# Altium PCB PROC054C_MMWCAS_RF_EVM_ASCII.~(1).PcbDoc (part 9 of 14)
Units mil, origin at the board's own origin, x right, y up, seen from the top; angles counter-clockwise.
Board outline 6299.21 x 5370.07 mil, 8 copper layers (L1 TOP, L2 GND, L3 SIGNAL 1, L4 GND, L5 SIGNAL 2, L6 SIGNAL 3, L7 GND, L8 BOTTOM), stack 53.5 mil thick; 775 components, 552 nets, 2648 pads, 7845 vias.
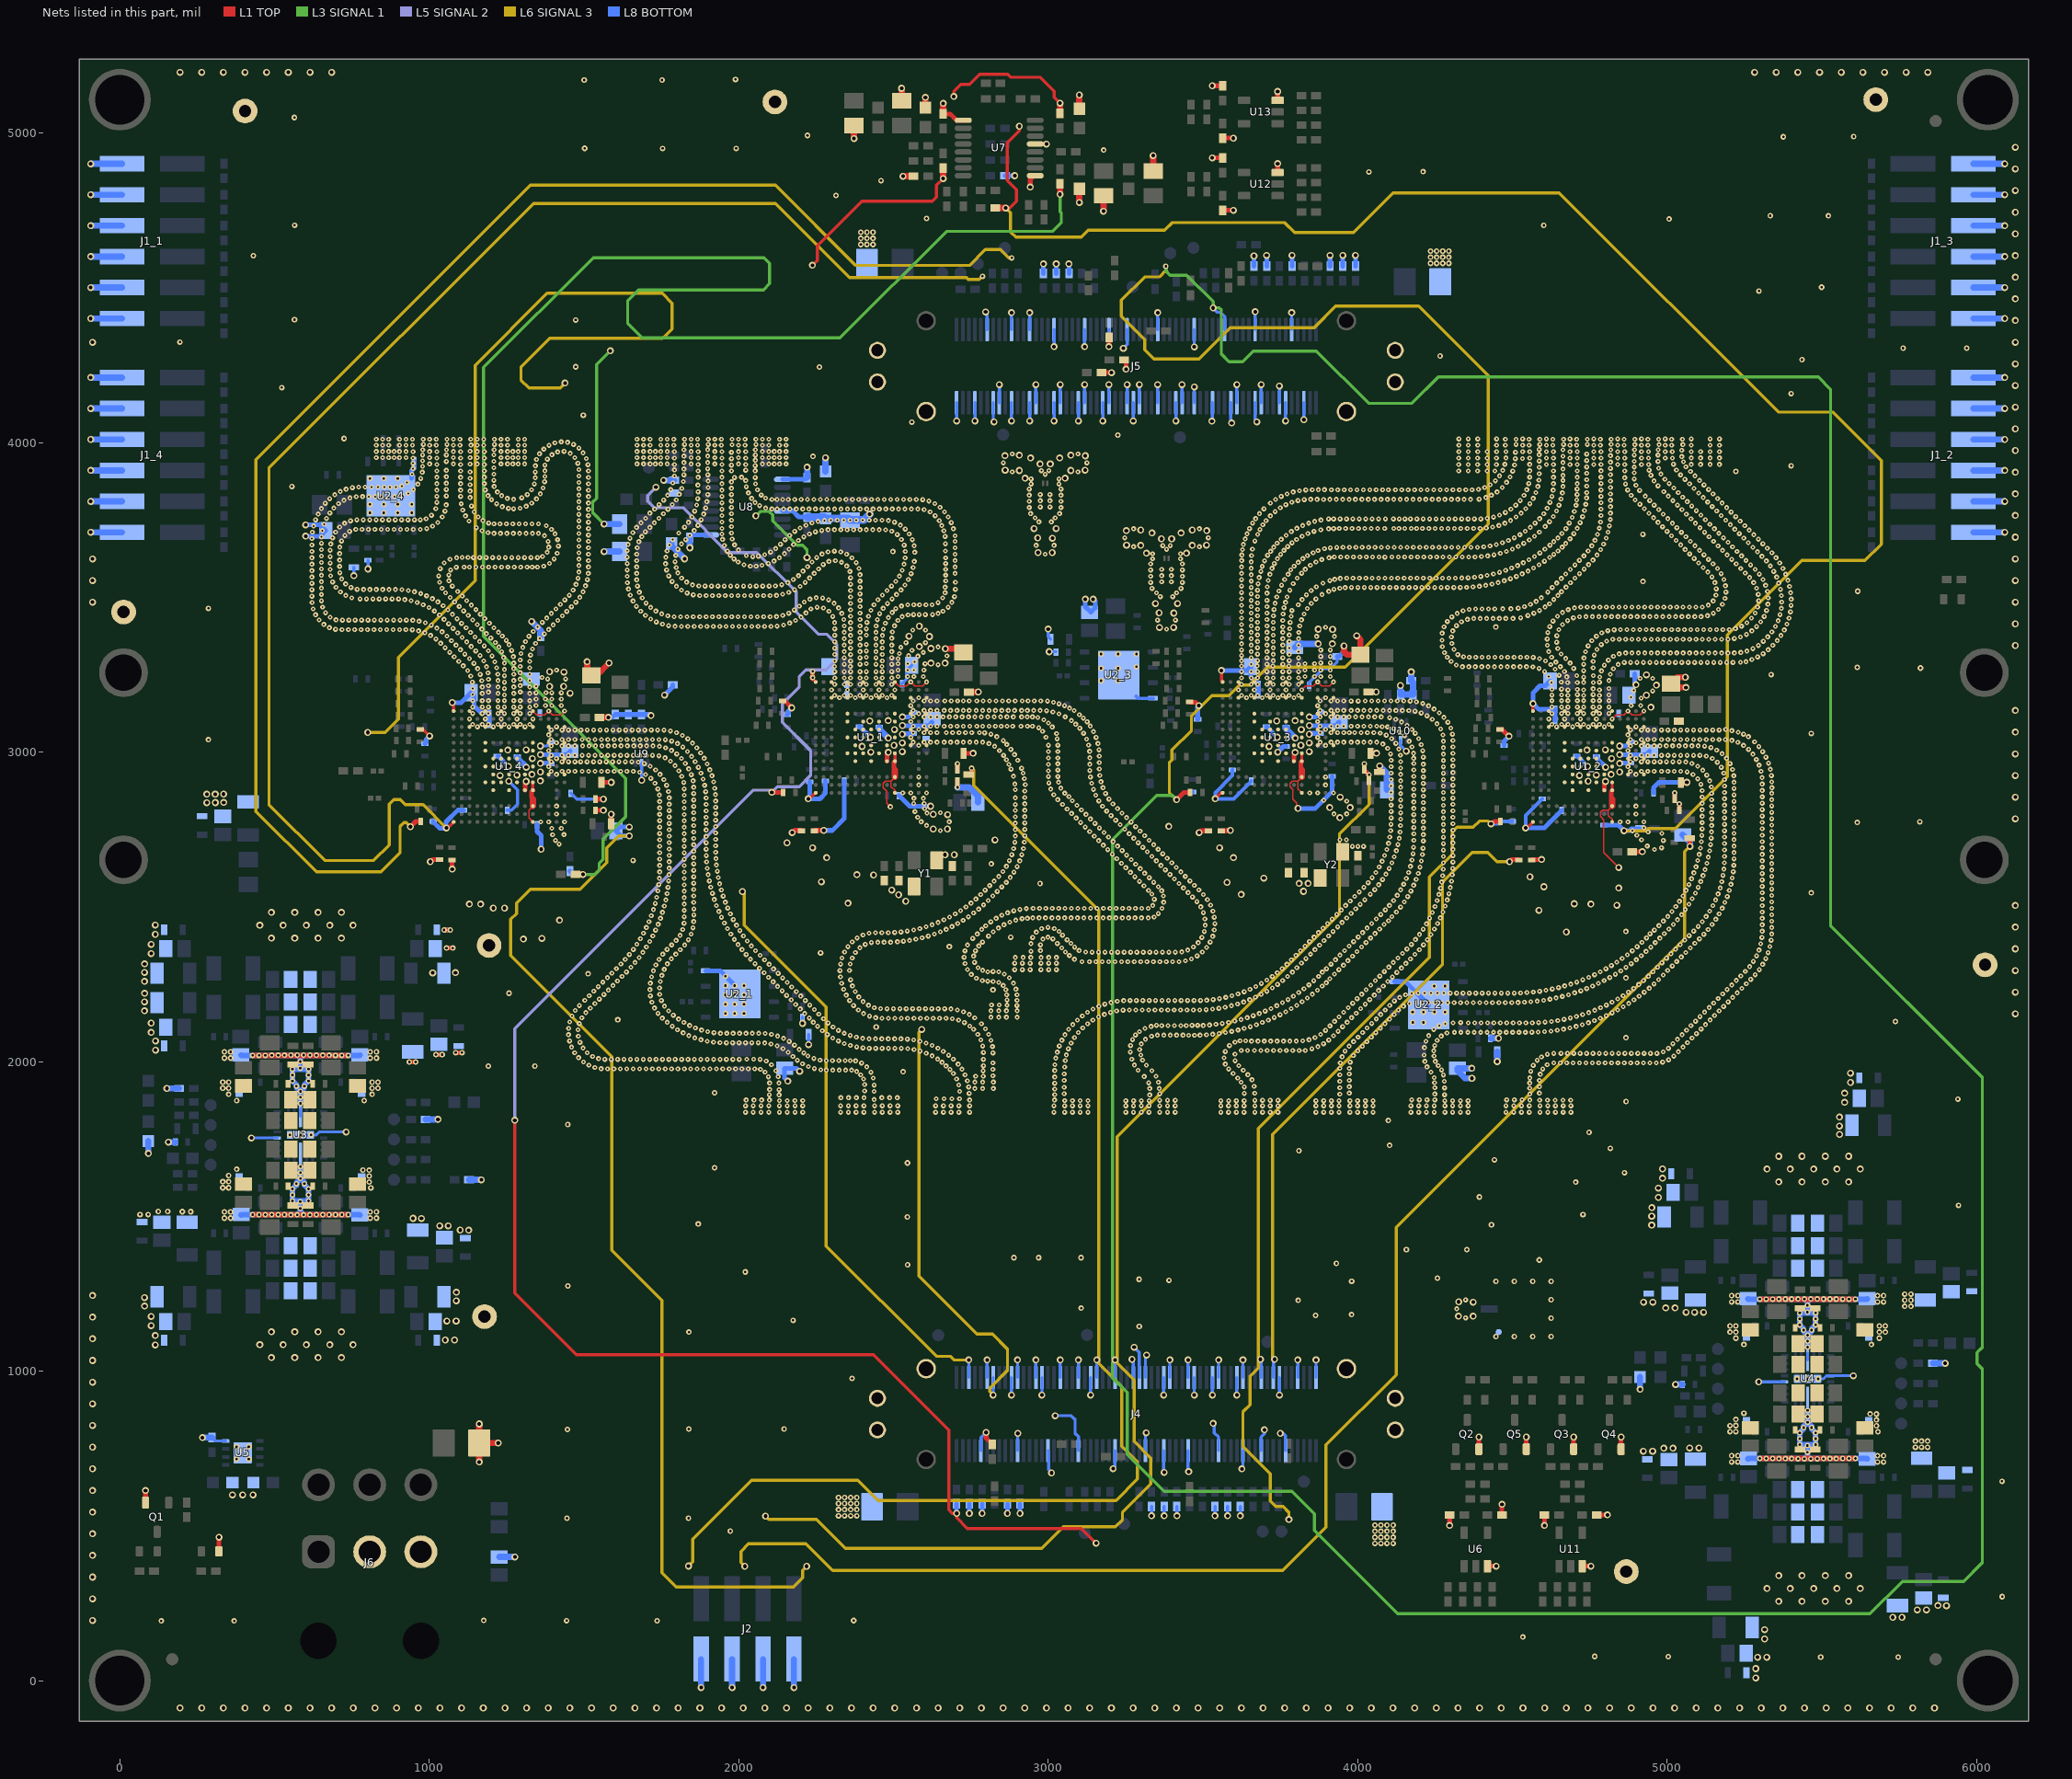
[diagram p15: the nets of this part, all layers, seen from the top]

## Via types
v1: diameter 13.77/15.74 (per signal layer), hole 5.9, L1 TOP to L2 GND, tented both sides, 5522 vias
v2: diameter 22.4, hole 12.2, L1 TOP to L8 BOTTOM, tented both sides, 1522 vias
v3: diameter 18, hole 8, L1 TOP to L8 BOTTOM, tented both sides, 727 vias
v4: diameter 18, hole 7.87, L1 TOP to L8 BOTTOM, tented top, 50 vias
v5: diameter 24, hole 12, L1 TOP to L8 BOTTOM, tented both sides, 13 vias
v6: diameter 19.68, hole 7.87, L1 TOP to L8 BOTTOM, tented top, 10 vias
v7: diameter 13.77/15.74 (per signal layer), hole 5.9, L1 TOP to L2 GND, tented top, 1 vias

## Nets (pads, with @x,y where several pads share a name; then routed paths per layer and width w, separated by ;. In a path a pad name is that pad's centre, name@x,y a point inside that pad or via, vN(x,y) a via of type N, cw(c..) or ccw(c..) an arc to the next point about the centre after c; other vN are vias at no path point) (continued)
GND: (continued)
  other v1: 4302.03,3293.21 4761.3,3293.07 2361.36,3294.31 4607.12,3294.44 1176.12,3294.76 2310.19,3294.52 2463.73,3294.69 3625,3295 3727.55,3295.32 3778.73,3295.48 3676.36,3295.67 4810.13,3296.99 1293.92,3297.69 5273.94,3299.28 1129.92,3301.76 2514.91,3302.12 4588,3302.28 4672.25,3302.38 2340.87,3304.39 2392.04,3304.39 2443.23,3304.39 2494.41,3304.39 3655.87,3304.39 3707.04,3304.39 3758.23,3304.39 3809.41,3304.39 4731.5,3304.16 1240.19,3305.75 2412.55,3306.28 4360.98,3306.4 4381.65,3306.4 4402.32,3306.4 4422.99,3306.4 4443.66,3306.4 4464.33,3306.4 4485,3306.4 4505.67,3306.4 4526.34,3306.4 4547.01,3306.4 4567.67,3306.06 4627.18,3306.36 4289.5,3306.5 5292.9,3307.5 1080.42,3307.88 1271.44,3308.32 4342,3308 3881.09,3308.94 3911.77,3308.94 1202.52,3310.38 2579.46,3310.11 4826.52,3309.57 2549.28,3311.33 2672.88,3311 1164.35,3311.76 3625,3312 4764.92,3313.42 1326.93,3313.59 2310.19,3315.19 2361.36,3314.98 2463.73,3315.36 4323.73,3314.9 1115.3,3316.38 3676.36,3316.34 3727.55,3315.99 3778.73,3316.15 4657.68,3317.04 1296.54,3318.19 4845.59,3317.55 5310.67,3318.07 2519.3,3318.51 4866.07,3320.39 4886.74,3320.4 4907.41,3320.4 4928.08,3320.4 4948.75,3320.4 4969.42,3320.4 4990.09,3320.4 5010.76,3320.4 5031.43,3320.4 5052.1,3320.4 5072.77,3320.4 5093.44,3320.4 5114.11,3320.4 5134.78,3320.4 5155.45,3320.4 5176.12,3320.4 5196.79,3320.4 5217.46,3320.4 2596.3,3322.1 4280.75,3321.51 5238.08,3321.78 1065.8,3322.5 1233.97,3323.98 4736.21,3324.29 2340.87,3325.06 2392.04,3325.06 2443.23,3325.06 2494.41,3325.06 3655.87,3325.06 3707.04,3325.06 3758.23,3325.06 3809.41,3325.06 4617.8,3324.78 5258.24,3326.37 1150.09,3326.71 2412.55,3326.95 1191.01,3327.55 1266.15,3328.31 2559.91,3329.05 3625.19,3329.64 3881.09,3329.61 3911.77,3329.61 1100.69,3330.99 5326.95,3330.81 4311.43,3331.51 4773.84,3332.07 1333.33,3333.24 5277.42,3334.05 4646.86,3334.65 2310.19,3335.86 2361.36,3335.65 2463.94,3336.02 1051.18,3337.12 3676.36,3337.01 3727.55,3336.66 3778.73,3336.82 1302.22,3338.06 2523.91,3338.46 1225.21,3339.7 2644,3339.89 1135.47,3341.33 4273.84,3340.99 1177.23,3342.95 4744.67,3343.14 4613.08,3344.9 5295.17,3344.65 5341.75,3345.24 1086.07,3345.61 2340.87,3345.73 2392.04,3345.73 2443.23,3345.73 2494.41,3345.73 3655.87,3345.73 3707.04,3345.73 3758.23,3345.73 3809.41,3345.73 1257.52,3347.09 2412.55,3347.62 4787.42,3347.65 3625.19,3350.31 1343.4,3351.29 4304.52,3350.99 1036.57,3351.73 2540.8,3353.49 1213.52,3353.77 2603.43,3353.58 4643.23,3355 1120.85,3355.95 2361.36,3356.32 2463.73,3356.03 1310.81,3356.86 2310.19,3356.53 3727.55,3357.33 3778.73,3357.49 1162.61,3357.57 3676.36,3357.68 5311.03,3357.9 4804.88,3358.72 1071.45,3360.23 4756.59,3360.03 5355.82,3360.38 1249,3361 4272.55,3361.62 4824.81,3364.21 1021.15,3365.5 4845.47,3364.72 4866.14,3364.72 4886.81,3364.72 4907.48,3364.72 4928.15,3364.72 4948.82,3364.72 4969.49,3364.72 4990.16,3364.72 5010.83,3364.72 5031.5,3364.72 5052.17,3364.72 5072.84,3364.72 5093.51,3364.72 5114.18,3364.72 5134.85,3364.72 5155.52,3364.72 5176.19,3364.72 5196.86,3364.75 2340.87,3366.4 2392.04,3366.4 2443.23,3366.4 3655.87,3366.4 3707.04,3366.4 3758.23,3366.4 3809.41,3366.4 4612.55,3365.57 1356.76,3367.07 5217.43,3366.81 1198.9,3368.39 2494.41,3367.88 1106.24,3370.56 3625.19,3370.98 1147.99,3372.19 4303.23,3371.62 5237.41,3372.09 5325.61,3372.56 1322.13,3374.16 3867.54,3374 3925.32,3374 4771.56,3374.29 1056.84,3374.84 1236,3375 4643.91,3375.66 1003.94,3376.95 2310.19,3377.29 2361.36,3377.02 2464.04,3376.7 5368.24,3376.9 2412.55,3377.64 3676.36,3378.35 3727.55,3378 3778.77,3378.16 5256.32,3380.44 1371.38,3381.69 1184.29,3383 4273.49,3384.45 1091.62,3385.18 4789.11,3385.21 985.27,3385.81 4614.64,3386.13 1133.38,3386.8 1223.45,3387.22 2340.87,3387.07 2392.04,3387.07 2443.23,3387.07 3655.87,3387.07 3707.04,3387.07 3758.23,3387.07 3809.92,3387.06 2496.7,3388.42 5338.86,3388.43 1041.41,3388.6 1335.89,3389.58 965.52,3391.92 3625.19,3391.65 4307.31,3391.88 4808.52,3392.32 5273.68,3391.67 2562.57,3394.44 2603.42,3394.43 945.1,3395.14 4650.08,3395.38 4828.97,3395.31 4849.64,3395.4 4870.31,3395.4 4890.98,3395.4 4911.65,3395.4 4932.32,3395.4 4952.99,3395.4 4973.66,3395.4 4994.33,3395.4 5015,3395.4 5035.67,3395.4 5056.34,3395.4 5077.01,3395.4 5097.68,3395.4 5118.35,3395.4 5139.02,3395.4 5159.69,3395.4 5180.36,3395.4 5378.83,3394.65 717.74,3395.66 738.41,3395.66 759.08,3395.66 779.75,3395.66 800.42,3395.66 821.09,3395.66 841.76,3395.66 862.43,3395.66 883.1,3395.66 903.77,3395.66 924.44,3395.66 1385.99,3396.3 5201.03,3395.64 697.09,3396.64 2467.23,3397.12 3382.46,3397.41 1169.67,3397.62 2310.19,3397.96 2361.36,3397.69 2412.58,3398.31 3676.36,3399.02 3727.55,3398.67 3780.31,3398.78 5221.39,3399.18 1024.47,3400.44 1077.01,3399.79 1118.76,3401.42 677.19,3402.22 1208.84,3401.83 3896.43,3402.88 1350.51,3404.2 4279.26,3404.3 3758.23,3404.87 5289.08,3405.45 1794,3406.49 1814.67,3406.34 1835.34,3406.34 1856.01,3406.34 1876.68,3406.34 1897.35,3406.34 1918.02,3406.34 1938.69,3406.34 1959.36,3406.34 1980.03,3406.34 2000.7,3406.34 2021.37,3406.34 2042.04,3406.34 2062.71,3406.34 2083.38,3406.34 2104.05,3406.34 4621.07,3405.77 5350,3405.83 2124,3407 5240.6,3406.82 2340.87,3407.74 2392.04,3407.74 2443.88,3407.73 2503.47,3407.95 3655.87,3407.74 3707.04,3407.74 3812.92,3407.51 1773.44,3408.63 4319.29,3408.73 1006.25,3410.21 1400.61,3410.92 2144.96,3410.74 659.21,3412.42 1155.06,3412.24 3625.19,3412.32 4662.09,3412.2 1753.31,3413.31 5387.48,3413.42 1062.39,3414.41 1104.15,3416.03 1194.22,3416.45 2164.71,3416.84 2473.77,3416.73 987.01,3417.75 2361.36,3418.36 5257.83,3418.24 1365.12,3418.81 2309.82,3418.62 2414.45,3418.89 3727.55,3419.34 3782.1,3419.1 1733.91,3420.44 3676.36,3419.69 4335.92,3421 5302.86,3420.86 4289.91,3422.02 967.01,3422.98 4631.55,3423.59 2183.51,3425.44 4678.3,3425.04 5358.87,3424.51 719.17,3426.34 739.84,3426.34 760.51,3426.34 781.18,3426.34 801.85,3426.34 822.52,3426.34 843.19,3426.34 863.86,3426.34 884.53,3426.34 905.2,3426.34 925.87,3426.34 946.54,3425.81 1415.22,3425.53 2514.37,3425.51 3353.57,3426.29 3411.35,3426.29 3758.23,3425.54 644.17,3426.59 1140.44,3426.85 3818.56,3427.4 698.54,3427.55 2339.36,3428.35 2392.04,3428.41 2447.97,3427.99 3655.87,3428.41 3707.04,3428.41 1047.78,3429.02 4355.06,3428.82 1715.54,3429.91 1089.53,3430.65 1179.61,3431.07 4375.52,3431.71 4396.19,3431.72 4416.86,3431.72 4437.53,3431.72 4458.2,3431.72 4478.87,3431.72 4502,3432 1379.74,3433.43 3625.19,3432.99 5272.72,3432.57 5394.09,3433.01 4527,3434 4697.09,3433.64 2483.48,3434.98 679.51,3435.63 2201.04,3436.39 1791.19,3437.37 1811.86,3437.02 1832.53,3437.02 1853.2,3437.02 1873.87,3437.02 1894.54,3437.02 1915.21,3437.02 1935.88,3437.02 1956.55,3437.02 1977.22,3437.02 1997.89,3437.02 2018.56,3437.02 2039.23,3437.02 2059.9,3437.02 2080.57,3437.02 2101.24,3437.02 4304.55,3436.6 2121.9,3437.8 2303.88,3438.42 2528,3438 4717.39,3437.52 4738.06,3437.72 4758.73,3437.72 4779.4,3437.72 4800.07,3437.72 4820.74,3437.72 4841.41,3437.72 4862.08,3437.72 4882.75,3437.72 4903.42,3437.72 4924.09,3437.72 4944.76,3437.72 4965.43,3437.72 4986.1,3437.72 5006.77,3437.72 5027.44,3437.72 5048.11,3437.72 5068.78,3437.72 5089.45,3437.72 5110.12,3437.73 5313.82,3438.38 2361.36,3439.03 2419.25,3439 3785.09,3438.88 4645.57,3438.78 1429.84,3440.15 1770.75,3440.42 3676.36,3440.36 3727.96,3440 1125.83,3441.47 4550.11,3441.23 5130.58,3440.67 1698.49,3441.59 2142.19,3441.71 1032.71,3443.17 2547,3443 632.51,3443.66 2565,3444 2583,3444 2603,3444 2626,3444 5365.32,3444.14 1074.91,3445.27 1164.99,3445.68 3759.18,3446.19 3826.75,3446.38 1751.01,3446.54 2455.66,3447.18 1394.36,3448.05 2333.23,3448.1 2644,3448 4321.68,3448.18 2161.61,3448.79 2392.04,3449.08 3655.87,3449.08 3707.04,3449.08 4569.45,3448.52 5149.64,3448.67 5284.88,3449.29 664.7,3450.05 2217.01,3449.51 2496.09,3451.36 4662.15,3451.12 5398.59,3453.18 3625.19,3453.66 1444.45,3454.76 1683.01,3455.29 2291.39,3454.89 2660,3455 1016.37,3455.84 1111.21,3456.08 1732.42,3455.57 4340.6,3456.49 3787.63,3457.45 2426.88,3458.21 4587.94,3457.75 5321.59,3457.54 2179.65,3458.88 1060.18,3459.77 1150.38,3460.3 2361.36,3459.7 4680.65,3460.34 3676.36,3461.03 3729.96,3460.57 4360.72,3461.25 5166.07,3461.22 2233.23,3462.32 4381.36,3462.4 4402.03,3462.4 4422.7,3462.4 4443.37,3462.4 624.65,3462.78 1408.97,3462.66 2507.43,3463.47 4469,3463 4495,3463 3837.34,3464.13 5369.24,3464.44 2273.6,3465.41 2466.7,3464.65 4519.13,3465.08 2322.71,3465.89 4700.49,3466.15 998.89,3466.87 1715.41,3467.32 3762.02,3466.66 655.07,3468.34 2253.1,3468.03 2677,3468 4721.04,3468.38 4741.71,3468.4 4762.38,3468.4 4783.05,3468.4 4803.72,3468.4 4824.39,3468.4 4845.06,3468.4 4865.73,3468.4 4886.4,3468.4 4907.07,3468.4 4927.74,3468.4 4948.41,3468.4 4969.08,3468.4 4989.75,3468.4 5010.42,3468.4 5031.09,3468.4 5051.76,3468.4 5072.43,3468.4 5093.1,3468.4 5292.81,3468.38 1459.07,3469.38 4605.38,3468.84 5113.76,3468.64 2392.04,3469.75 3655.87,3469.75 3707.04,3469.75 4539.21,3469.96 1096.6,3470.7 1669.46,3470.91 2195.85,3471.72 2526,3472 1044.46,3473.19 3625.19,3474.33 5400.92,3473.72 1135.76,3474.91 5133.5,3474.78 980.43,3476.17 2437.18,3476.13 2546,3476 2566,3476 2584,3476 2605,3476 2625,3476 3808.35,3475.9 1423.59,3477.28 4558.56,3477.24 5178.8,3477.5 5325.92,3477.75 4620,3479 2361.36,3480.37 2480.62,3479.93 3850.16,3480.35 2308.34,3480.74 3733.62,3480.92 1700.4,3481.53 3676.36,3481.7 620.94,3483.12 2644,3483 961.16,3483.64 1473.52,3484.16 2689,3484 3767,3484 1027.67,3485.23 1081.98,3485.32 2211.6,3485.11 5370.58,3485.06 4576.88,3486.82 1658.22,3488.25 5149.13,3488.3 651.37,3488.67 941.26,3489.23 5296.09,3488.79 1121.15,3489.53 2392.04,3490.42 3655.87,3490.42 3707.04,3490.42 1438.2,3491.89 2290.74,3491.58 2449.94,3492.39 920.91,3492.88 3820.4,3492.69 4634,3493 2230.11,3494.32 5401.09,3494.39 776.29,3494.66 796.96,3494.66 817.63,3494.66 838.3,3494.66 858.97,3494.66 879.64,3494.66 900.31,3494.55 2495.24,3494.55 3625.19,3495 3864.99,3494.75 1009.92,3495.82 5187.02,3496.47 749.35,3498.36 1688.01,3498.08 2270.98,3497.66 2659,3498 5326.71,3498.4 2250.33,3498.59 4593.9,3498.54 1067.37,3499.93 1486.29,3500.41 2361.36,3501.04 3738.91,3500.9 3772.01,3501.01 2697,3502 3362.42,3502.01 3402.5,3502.01 3676.36,3502.37 620.66,3503.78 1106.53,3504.15 991.34,3504.88 730.13,3505.96 1873.79,3505.75 1894.46,3505.72 1915.13,3505.72 1935.8,3505.72 1956.47,3505.72 1977.14,3505.72 1997.81,3505.72 2018.48,3505.72 2039.15,3505.72 2059.82,3505.72 2080.49,3505.72 2101.16,3505.72 2122,3506 4647,3506 5369.55,3505.71 1452.55,3506.77 1649.49,3506.99 2464.44,3507.13 5158.07,3506.94 1853.25,3508.1 3834.21,3508.07 651.34,3509.34 2509.85,3509.16 3885,3509 5294.77,3509.41 2142.07,3510.01 2392.04,3511.09 3655.87,3511.09 972.06,3512.34 3707.04,3513.43 1833.46,3514.05 1052.75,3514.55 2667,3515 3349.86,3514.57 3415.05,3514.58 5399.37,3514.99 2161.85,3516 3625.19,3515.67 712.88,3517.36 1678.7,3516.53 4614.34,3517.2 5190.19,3516.89 952.22,3518.15 1496.86,3518.18 4658.71,3518.19 1091.92,3518.76 3906.68,3519.48 5324.2,3518.92 3745.8,3520.39 931.97,3522.27 2361.36,3521.71 2479.05,3521.74 3849.63,3521.83 1464.71,3523.49 1815.03,3523.42 3676.56,3523.04 3781,3523 620.66,3524.45 2180.71,3524.46 2524.31,3523.93 787.43,3525.34 808.1,3525.34 828.77,3525.34 849.44,3525.34 870.11,3525.34 890.78,3525.34 911.44,3524.67 766.77,3526 2700,3526 3923.33,3525.81 5366.4,3526.14 1643.46,3526.76 5159.1,3527.59 1041.14,3529.44 3335.76,3528.76 3429.15,3528.77 3942.54,3529.46 5289.34,3529.36 651.34,3530.01 698.41,3532.12 746.95,3531.86 2392.04,3531.76 3655.87,3531.76 3959.59,3531.6 3980.26,3531.72 4000.93,3531.72 4021.6,3531.72 4042.27,3531.72 4062.94,3531.72 4083.61,3531.72 4104.28,3531.72 4124.95,3531.72 4145.62,3531.72 4166.29,3531.72 4186.96,3531.72 4207.63,3531.72 4228.3,3531.72 4248.97,3531.72 4269.64,3531.72 4290.31,3531.72 4310.98,3531.72 4331.65,3531.72 4352.31,3532.23 4628.96,3531.82 2667,3533 4673.32,3532.81 3708.09,3534.07 3866.49,3533.8 4372.93,3533.62 2198.34,3535.24 5395.81,3535.35 1074.44,3536.24 1672.77,3536.33 1798.57,3535.91 1891.41,3536.4 1912.08,3536.4 1932.75,3536.4 1953.42,3536.4 1974.09,3536.4 1994.76,3536.4 2015.43,3536.4 2036.1,3536.4 2056.77,3536.4 2077.44,3536.4 2098.11,3536.4 2493.67,3536.36 3625.19,3536.34 4393.48,3535.89 1505.05,3537.16 1870.74,3536.6 2118.76,3537.12 5188.72,3537.51 3754.24,3539.26 4413.91,3539.04 5318.55,3538.8 2537.23,3540.07 1850.44,3540.51 2139.09,3540.89 1474.04,3541.93 2361.36,3542.38 729.74,3543.32 4434.18,3543.06 3678.31,3543.64 3792,3544 620.66,3545.12 3888,3546 4643.57,3546.44 5361.18,3546.14 1640.23,3547.17 4687.94,3547.42 1033.01,3548.45 2158.57,3547.79 2214.46,3548.18 3331.11,3548.21 3433.81,3548.21 4454.27,3547.94 5154.47,3547.73 5280.02,3547.81 1831.68,3549.19 2700,3549 687.69,3549.79 3366.97,3550.07 3398.22,3550.07 651.34,3550.68 1784.64,3551.19 2392.04,3552.43 2507.59,3551.64 3655.87,3552.43 2668.7,3553.19 1063.46,3553.75 3910,3554 4474.13,3553.68 3711.22,3554.51 5390.46,3555.31 1510.72,3557.03 1670.38,3556.86 3625.19,3557.01 3764.18,3557.38 2176.73,3557.66 2548.13,3557.63 3926,3558 5183.55,3557.52 5309.9,3557.58 717.03,3559.61 4493.72,3560.26 3943.85,3561.12 4658.19,3561.05 1480.31,3561.63 1815.56,3562.13 3805,3562 3964.48,3562.4 3985.15,3562.4 4005.82,3562.4 4026.49,3562.4 4047.16,3562.4 4067.83,3562.4 4088.5,3562.4 4109.17,3562.4 4129.84,3562.4 4150.51,3562.4 4171.18,3562.4 4191.85,3562.4 4212.52,3562.4 4233.19,3562.4 4253.86,3562.4 4274.53,3562.4 4295.2,3562.4 4315.87,3562.4 4336.54,3562.45 4702.55,3562.04 2229.19,3562.68 2361.36,3563.05 4357.19,3563.21 3681.87,3564 5267.21,3564.03 4377.79,3564.92 5353.93,3565.49 620.66,3565.79 5145.04,3566.12 1639.66,3567.84 3331.11,3568.21 3433.81,3568.21 4398.29,3567.56 4513.02,3567.67 681.34,3569.46 1030.23,3568.93 1773.92,3568.86 2519.2,3568.74 2193.13,3570.25 3366.97,3570.07 3398.22,3570.07 651.34,3571.35 4418.65,3571.14 1063,3572 2668.66,3571.76 2392,3573.1 3655.87,3573.1 3716.4,3574.52 3775.55,3574.64 5298.46,3574.79 5383.35,3574.72 2556.84,3576.38 4438.82,3575.65 4531.98,3575.91 4672.8,3575.67 5174.86,3576.28 1513.78,3577.48 2243.81,3577.3 4717.17,3576.66 1670.34,3577.53 2699.34,3577.57 3625.19,3577.68 3819,3578 710.81,3579.33 1803.3,3578.77 5252.6,3578.65 4458.77,3581.07 1483.36,3582.07 5131.5,3581.74 2359.49,3583.64 3687.21,3583.97 5344.73,3584 2207.87,3584.74 4550.57,3584.94 620.66,3586.46 2528.19,3587.35 4478.45,3587.4 1068.84,3588.15 1766.8,3588.27 3331.11,3588.21 3433.81,3588.21 1639.66,3588.51 3783.7,3588.81 679.66,3590.06 2668.66,3590.43 3366.97,3590.07 3398.22,3590.07 4687.42,3590.28 5284.55,3590.08 3830.98,3591.06 4731.79,3591.27 651.34,3592.02 2258.43,3591.91 1035.39,3592.84 2388.55,3593.48 5162.94,3593.16 5237.98,3593.27 5374.53,3593.42 3655.87,3593.77 3723.58,3593.9 4497.81,3594.62 4568.75,3594.76 2563.25,3596.03 5116.88,3596.36 1087.34,3597.36 1798,3596.5 1112.49,3597.67 1129.94,3597.67 1150.61,3597.67 1171.28,3597.67 1191.95,3597.67 1212.62,3597.67 1233.29,3597.67 1253.96,3597.67 1274.63,3597.67 1295.3,3597.67 1315.97,3597.67 1332.59,3597.67 1349.21,3597.66 1514.34,3598.14 1670.34,3598.2 2699.34,3598.24 3625.19,3598.35 2222.49,3599.35 710.34,3599.99 3692,3600 1369.64,3600.8 2037.27,3601 2056,3601 2348.87,3601.38 3795,3601 5333.68,3601.47 1483.66,3602.74 4516.83,3602.71 2075.17,3603.71 3847.31,3603.73 2017.03,3605.17 4586.5,3605.36 4702.03,3604.9 5269.93,3604.69 2273.28,3606.29 4746.4,3605.89 620.66,3607.13 2534.38,3607.07 3331.11,3607.98 3433.81,3607.98 5148.59,3608.03 5223.37,3607.88 1639.66,3609.18 1763.56,3608.68 2095.08,3609.24 2668.66,3609.1 3731.01,3609.01 1388.19,3609.93 679.66,3610.73 1048,3611 5102.27,3610.97 5364.09,3611.26 2379.56,3612.09 4535.46,3611.67 651.34,3612.69 2332.06,3613.39 3808,3613 1998.29,3613.9 2237.1,3613.97 3655.88,3614.44 3865.16,3614.15 1794.04,3615.14 2291.51,3616.03 2567.26,3616.31 2114.06,3617.44 4603.78,3616.7 3699,3618 5320.89,3617.71 1514.34,3618.81 1670.34,3618.87 2312.03,3618.51 2699.34,3618.91 3625.28,3619.02 5255.32,3619.31 4716.65,3619.52 710.34,3620.66 4553.66,3621.47 4760.75,3620.77 3884.22,3622.15 1067,3623 1483.66,3623.41 5133.97,3622.65 5208.75,3622.5 1403.13,3624.2 1985,3624 3337.35,3624.4 3427.61,3624.4 3741,3625 3823,3625 5087.65,3625.59 2537.64,3627.48 620.66,3627.8 1088,3628 1142.51,3628.35 1163.18,3628.35 1183.85,3628.35 1204.52,3628.35 1225.19,3628.35 1245.86,3628.35 1266.53,3628.35 1287.2,3628.35 1307.87,3628.35 1328.54,3628.35 1349.21,3628.35 2131.73,3628.16 2251.9,3628.4 2365.84,3627.55 2668.66,3627.77 3907.62,3627.88 5352.1,3628.09 1106,3629 1125,3629 1764.19,3629.34 4620.56,3628.77 1639.66,3629.85 3924.65,3630.35 4088,3630 679.66,3631.4 2045,3631.34 3945.32,3630.72 3965.99,3630.72 3986.66,3630.72 4007.33,3630.72 4028,3630.72 4048.67,3630.72 4069.34,3630.72 4110.68,3630.72 4131.35,3630.72 4152.02,3630.72 4172.69,3630.72 4193.36,3630.72 4214.03,3630.72 4234.7,3630.72 4255.37,3630.72 4276.04,3630.72 4296.71,3630.72 4317.38,3630.72 4338.05,3630.72 4358.72,3630.72 4379.39,3630.75 1365.46,3632.06 4400.04,3631.67 4571.39,3632.09 651.34,3633.36 2063.68,3632.8 5306.6,3632.65 4420.58,3633.92 4731.26,3634.14 5240.7,3633.93 2024.66,3635 3657.06,3635.08 3838,3635 1796.41,3635.67 1973,3636 3709,3636 3626,3637 4440.94,3637.5 4773.77,3636.82 5119.35,3637.27 5194.13,3637.11 2083.74,3637.77 1514.34,3639.48 2348.84,3639.3 2990.1,3639.42 3751,3639 4634,3639 1670.34,3639.54 2269.08,3639.89 2699.34,3639.58 5073.04,3640.2 710.34,3641.33 2147.77,3641.2 3337.35,3640.67 3427.61,3640.67 1413.11,3642.31 4461.03,3642.37 1483.66,3644.08 3856,3644 4588.62,3643.51 5338.66,3643.8 1380.86,3645.85 2102.66,3646.12 2568.84,3646.02 2288.49,3647 2329.53,3646.69 5291.99,3647.26 620.66,3648.47 2538.13,3648.15 1963.06,3649.14 2309.03,3649.31 3719.01,3649.01 4480.76,3648.53 5226.09,3648.54 1768.37,3649.58 2668,3650 4648,3650 4744.95,3649.62 1639.82,3650.51 3872,3651 679.66,3652.07 3762,3652 5104.74,3651.88 5179.52,3651.73 1999.09,3653.09 651.34,3654.03 3628,3654 4785.25,3654.01 1803.42,3655.12 3382.48,3655.22 3660.23,3655.5 5058.42,3654.82 2162.44,3655.75 4500.05,3655.95 4605.31,3655.7 3893,3657 2119.85,3657.58 5324.13,3658.5 1514.34,3660.15 1671.68,3660.17 2699.34,3660.25 3911.63,3659.88 3932.25,3661.37 3952.92,3661.4 3973.59,3661.4 3994.26,3661.4 4014.93,3661.4 4035.6,3661.4 4056.27,3661.4 4076.94,3661.4 4097.61,3661.4 4118.28,3661.4 4138.95,3661.4 4159.62,3661.4 4180.29,3661.4 4200.96,3661.4 4221.63,3661.4 4242.3,3661.4 4262.97,3661.4 4283.64,3661.4 4304.31,3661.4 4324.98,3661.4 4345.65,3661.4 4366.32,3661.4 710.9,3661.99 1386,3662 3729,3662 4386.98,3661.63 4661,3662 5277.37,3661.88 4407.59,3663.2 5211.47,3663.16 3276.3,3663.67 3488.62,3663.65 3773.88,3664.32 1483.66,3664.75 4518.83,3664.59 1417.25,3665.73 4428.04,3666.22 4756.91,3666.49 5164.9,3666.34 1953.55,3667.49 2566.82,3666.59 3370.48,3667.22 3394.48,3667.22 5090.12,3666.5 2961.21,3668.3 3018.99,3668.3 620.66,3669.14 1775.96,3668.81 2534.71,3668.53 4621.43,3668.65 5043.8,3669.44 1986.56,3669.53 2177.07,3670.36 1642.54,3671 3631,3671 4448.22,3670.7 1814.69,3672.45 2134.98,3671.67 4795.09,3672.19 681.55,3672.66 2668,3673 5309.51,3673.12 4537.01,3674.43 4672.29,3673.9 651.34,3674.7 3740.01,3675.01 3788.01,3675.86 4468.03,3676.6 5262.75,3676.5 5196.85,3677.77 1677.34,3680.05 4634,3680 1384.1,3680.62 1514.34,3680.82 2699.34,3680.92 5075.51,3681.11 5150.29,3680.96 716.27,3681.95 3668,3682 2192.74,3683.84 4487.37,3683.89 5029.19,3684.05 1483.66,3685.42 4554.52,3685.41 4766.98,3684.54 1414.46,3686.21 1786.72,3686.46 2149.6,3686.29 2560.84,3686.38 1829,3686.5 1947.69,3687.31 2525.86,3687.21 3753.32,3687.25 3802.9,3686.94 5294.9,3687.73 1978.81,3688.69 3637,3689 4686.23,3689.16 620.71,3689.81 1648.58,3690.77 4803.2,3691.2 5248.14,3691.11 687.43,3692.47 4647,3692 5182.24,3692.39 3247.42,3692.56 3517.5,3692.54 4506.14,3692.55 651.65,3695.37 2209.92,3695.33 5060.89,3695.73 5135.67,3695.58 1686.5,3696.5 2667,3697 3820.74,3697.37 4571.29,3697.5 1371.95,3699.29 2699.01,3699 5014.57,3698.67 726.93,3699.67 1842.07,3700.37 1514.34,3701.49 2164.6,3700.51 3769.13,3700.56 5280.28,3702.35 2512.24,3702.76 3676.95,3703.28 4524.25,3702.52 4775.06,3703.56 1406.29,3705.2 1945.72,3704.61 2228.36,3704.66 2551.12,3704.62 3642.87,3705.3 1483.66,3706.09 3839.48,3706.1 4660.25,3705.96 4698.77,3705.6 5233.52,3705.73 1209.35,3706.66 1230.02,3706.66 1250.69,3706.66 1271.36,3706.66 1292.03,3706.66 1312.7,3706.66 1333.37,3706.66 1352.64,3706.66 1805.76,3707.44 5167.62,3707 1976.4,3707.89 1190,3708.97 1657.78,3709.28 622.34,3710.42 5046.27,3710.35 5121.05,3710.19 697.07,3710.76 4587.24,3710.65 4809.52,3710.88 1698.2,3711.51 2247.8,3711.7 742.45,3713.31 2180.93,3713.18 3785.98,3712.53 3858.94,3713.05 4999.96,3713.28 2494.62,3713.56 4541.6,3713.75 1170.28,3715.16 2663,3715 654.36,3715.86 1855.9,3715.73 2267.94,3716.33 5265.67,3716.96 2288.5,3718.49 2474.53,3718.44 3880.97,3718.16 762.18,3719.47 2309.17,3718.66 2329.84,3718.66 2350.51,3718.66 2371.18,3718.66 2391.85,3718.66 2412.52,3718.66 2433.19,3718.66 2453.86,3718.66 3684.54,3719 782.85,3719.66 803.52,3719.66 824.19,3719.66 844.86,3719.66 865.53,3719.66 886.2,3719.66 906.87,3719.66 927.54,3719.66 948.21,3719.66 970.92,3719.66 1394.84,3719.85 5218.91,3720.34 2538.05,3720.63 3276.3,3721.45 3488.62,3721.43 3906.35,3721.46 991.42,3722.27 1514.34,3722.16 2693.82,3721.79 3650.68,3722.28 3922.61,3722 4672.98,3722.25 5153.01,3721.62 1945.72,3722.61 3803.75,3723.08 3940.69,3722.72 3961.36,3722.72 3982.03,3722.72 4002.7,3722.72 4023.37,3722.72 4044.04,3722.72 4064.71,3722.72 4087.38,3722.72 4117.05,3722.72 4133.72,3722.72 4152.39,3722.72 4173.06,3722.72 4190.73,3722.72 4209.4,3722.72 4230.07,3722.72 4250.74,3722.72 4271.41,3722.72 4292.08,3722.72 4312.75,3722.72 4333.42,3722.72 4354.09,3722.72 4374.76,3722.72 4395.43,3722.72 4709.8,3723.08 4781.05,3723.34 2198.47,3724.11 4416.07,3723.82 1152.1,3725.01 5031.66,3724.96 5106.44,3724.81 1669.88,3726.04 1712.82,3726.13 1824.62,3726.46 4558.11,3726.19 710.11,3726.8 1483.66,3726.76 4436.49,3727 4985.34,3727.9 1976.4,3728.56 4606.37,3728.85 1010.62,3729.93 626.29,3730.71 4813.99,3731.06 1377.92,3731.72 1868.03,3732.47 2656,3732 3822.33,3732.15 4456.49,3732.21 5251.05,3731.58 2217.04,3733.19 2522,3733.66 3693.93,3734.3 5204.29,3734.96 659.83,3735.79 5138.39,3736.24 1209.35,3737.33 1228.62,3737.34 1249.29,3737.34 1269.96,3737.34 1290.63,3737.34 1311.3,3737.34 1331.97,3737.34 1352.64,3737.34 726.43,3739.48 4475.87,3739.42 5091.82,3739.42 1191.7,3740.12 2236.44,3740.31 3660.38,3740.01 3841.58,3739.67 4573.69,3739.77 4683.99,3739.74 5017.04,3739.58 1684.23,3740.92 1727.43,3740.74 2686.79,3741.23 4719.24,3741.46 1027.3,3742.15 1837.72,3742.45 1514.34,3742.83 1945.72,3743.28 2503.57,3743.01 4970.72,3742.52 2970.06,3744.02 3010.14,3744.02 4620.19,3744.22 4784.89,3743.65 2256.47,3745.41 1128.67,3746.36 3861.39,3745.58 5236.44,3746.19 1483.66,3747.43 745.48,3747.51 1172.7,3748.25 2276.92,3748.43 2483.57,3748.25 2648.14,3747.68 3704.1,3748.02 1976.4,3749.23 2297.57,3749.34 2318.24,3749.34 2338.91,3749.34 2359.58,3749.34 2380.25,3749.34 2400.92,3749.34 2421.59,3749.34 2442.26,3749.34 2462.93,3749.34 4494.41,3748.54 632.51,3750.42 765.95,3750.34 786.62,3750.34 807.29,3750.34 827.96,3750.34 848.63,3750.34 869.3,3750.34 889.97,3750.34 910.64,3750.34 931.31,3750.34 951.98,3750.34 970.92,3750.34 1878.35,3750.38 3881.61,3749.86 5189.68,3749.57 5123.77,3750.85 4816.57,3751.57 3906.32,3753.12 3922.77,3753.4 3943.44,3753.4 3964.11,3753.4 3984.78,3753.4 4005.45,3753.4 4026.12,3753.4 4046.79,3753.4 4067.46,3753.4 4090.13,3753.4 4115.8,3753.4 4134.47,3753.4 4153.14,3753.4 4170.81,3753.4 4191.48,3753.4 4212.15,3753.4 4232.82,3753.4 4253.49,3753.4 4274.16,3753.4 4294.83,3753.4 4315.5,3753.4 4336.17,3753.4 4356.84,3753.4 4377.51,3753.4 4398.18,3753.43 989.88,3753.98 3670.39,3754.34 5002.43,3754.19 5077.21,3754.04 667.95,3754.8 1742.05,3755.36 4418.78,3755.05 4588.51,3754.5 1698.85,3755.54 2957.5,3756.58 3022.69,3756.59 4956.11,3757.13 4693.15,3758.27 2677.09,3759.48 4439.05,3759.1 4511.95,3759.49 1041.67,3759.86 1157.84,3759.84 1848.72,3759.95 4632.32,3760.96 4727.01,3760.62 5221.82,3760.81 1116.9,3763.35 1514.34,3763.5 3717.91,3763.4 1945.72,3763.95 2634.9,3763.55 4786.52,3764.26 5175.06,3764.19 1007.15,3765.34 5109.16,3765.47 4458.7,3765.52 1483.66,3768.1 640.91,3769.3 1886.72,3769.28 4987.81,3768.81 5062.59,3768.65 1756.66,3769.97 1976.4,3769.9 4601.66,3770.45 2943.4,3770.77 3036.79,3770.78 3683.04,3770.68 1713,3772 4528.29,3772.15 4817.26,3772.23 4941.49,3771.75 678.58,3772.53 4477.45,3774.23 5207.2,3775.43 1145.02,3776.06 2618.43,3776.03 2664.91,3776.18 3733.26,3777.25 4700.38,3777.64 1050.44,3778.57 1857.46,3778.68 4642.61,3778.88 5160.44,3778.81 4733.06,3780.38 5094.54,3780.08 1108.23,3782.11 4973.19,3783.43 5047.97,3783.27 1514.34,3784.17 2599.18,3783.57 1728.08,3784.77 1771.28,3784.59 1945.72,3784.62 4495.03,3785.09 4786.58,3784.93 1272.74,3785.9 2107.01,3785.66 2123.88,3785.66 2144.55,3785.66 2165.22,3785.66 2185.89,3785.66 2206.56,3785.66 2227.23,3785.66 2247.9,3785.66 2268.57,3785.66 2289.24,3785.66 2309.91,3785.66 2330.58,3785.66 2351.25,3785.66 2371.92,3785.66 2392.59,3785.66 2413.26,3785.66 2433.93,3785.66 2454.6,3785.66 2475.27,3785.66 2495.94,3785.66 2516.61,3785.66 2537.28,3785.66 2557.95,3785.66 2578.62,3785.66 3697.03,3785.9 4543.26,3786.4 4926.88,3786.36 651.4,3787.12 1020.73,3786.54 1255.62,3787.36 1293.3,3788.02 2086.59,3788.34 4612.71,3787.92 691.52,3788.65 1483.66,3788.77 1893.06,3788.95 3750.1,3789.23 2938.75,3790.22 3041.45,3790.22 5192.59,3790.04 1976.4,3790.57 2650.44,3790.93 2974.61,3792.08 3005.86,3792.08 1235.71,3792.93 4817.26,3792.9 5145.83,3793.42 1312.99,3794.3 1136.3,3794.8 5079.92,3794.7 2067.49,3796.24 1863.81,3798.35 4511.2,3797.97 4650.96,3797.79 4705.6,3797.64 4958.58,3798.04 5033.36,3797.89 1054.67,3798.81 1742.69,3799.38 3768.2,3799.21 1785.51,3799.58 4737.34,3800.6 4912.26,3800.98 1102.93,3802.09 1217.36,3802.44 4556.4,3802.35 706.7,3802.68 2633.48,3802.76 663.83,3803.63 1330.99,3804.48 3718.06,3804.3 1514.34,3804.84 1945.72,3805.29 5177.97,3804.66 4786.58,3805.6 1024.36,3806.89 2052.5,3806.5 3787.34,3807.03 4621.49,3806.63 5131.21,3808.04 1483.66,3809.44 1897.3,3809.18 5065.31,3809.31 2938.75,3810.22 3041.45,3810.22 1976.4,3811.24 2614.56,3811.07 2974.61,3812.08 3005.86,3812.08 3807.24,3812.59 4525.64,3812.75 4943.96,3812.66 5018.74,3812.5 724.19,3813.69 1757.28,3814.03 4817.26,3813.57 1201.32,3815.48 1798,3815 4708,3815 4897,3815 2107.01,3816.34 2123.66,3816.34 2141.66,3816.34 2160.33,3816.34 2181,3816.34 2201.67,3816.34 2222.34,3816.34 2243.01,3816.34 2263.68,3816.34 2284.35,3816.34 2305.02,3816.34 2325.69,3816.34 2346.36,3816.34 2367.03,3816.34 2387.7,3816.34 2408.37,3816.34 2429.04,3816.34 2449.71,3816.34 2470.38,3816.34 2491.05,3816.34 2511.72,3816.34 2532.39,3816.34 2553.06,3816.34 2573.73,3816.34 2594.38,3815.56 3735.09,3816.02 3827.66,3815.83 3890,3816 1272.74,3816.58 3848.31,3816.72 3868.98,3816.72 3910.32,3816.72 3930.99,3816.72 3951.66,3816.72 3972.33,3816.72 3993,3816.72 4013.67,3816.72 4034.34,3816.72 4055.01,3816.72 4075.68,3816.72 4096.35,3816.72 4117.02,3816.72 4137.69,3816.72 4158.36,3816.72 4179.03,3816.72 4199.7,3816.72 4220.37,3816.72 4241.04,3816.72 4261.71,3816.72 4282.38,3816.72 4303.05,3816.72 4323.72,3816.72 4344.39,3816.72 4365.06,3816.72 4392.65,3817.2 4657.26,3817.48 1346.52,3818.11 678.07,3818.61 1867.65,3818.66 5163.36,3819.27 1252.29,3819.61 2041.6,3819.84 4567.4,3819.85 743.42,3821.27 2086.82,3820.75 4739.81,3821.13 1298.93,3821.67 1131.82,3822.68 4414.4,3822.7 5116.6,3822.65 5050.69,3823.93 763.72,3825.15 784.39,3825.66 805.06,3825.66 825.73,3825.66 846.4,3825.66 867.07,3825.66 887.74,3825.66 1024.36,3825.96 1101.14,3825.96 1514.34,3825.51 1945.72,3825.96 3753.18,3826.02 4627.86,3826.29 4786.58,3826.27 4929.35,3827.27 5004.12,3827.12 912.43,3828.27 1055.04,3827.56 1190.01,3828.45 1233.61,3828.46 1483.66,3830.11 1770.23,3830.14 2938.75,3830.22 3041.45,3830.22 4432.5,3829.95 4537.64,3829.58 4884.19,3829.54 2072.77,3830.53 694.22,3831.51 1316.74,3832.16 1900,3832 1976.4,3831.91 2974.61,3832.08 3005.86,3832.08 4709,3832 1808,3833 3772.17,3834.18 4817.26,3834.24 5148.74,3833.89 1358.94,3834.64 931.63,3835.93 5101.98,3837.27 2031.15,3837.67 4661.45,3837.72 4576.07,3838.62 4740.48,3838.71 5036.08,3838.54 1219.84,3840.34 3791.87,3840.44 1869,3841 4450.45,3840.5 712.08,3841.93 4989.51,3841.73 1131.82,3843.35 3812.09,3844.73 4911.14,3845.49 1514.34,3846.18 1024.36,3846.63 1101.14,3846.63 1181.01,3847.06 1330.71,3847.4 1945.72,3846.63 2060.59,3847.23 3832.63,3847.01 3853.3,3847.4 3915.31,3847.4 3935.98,3847.4 3956.65,3847.4 3977.32,3847.4 3997.99,3847.4 4018.66,3847.4 4039.33,3847.4 4060,3847.4 4080.67,3847.4 4099.34,3847.4 4122.01,3847.4 4142.68,3847.4 4163.35,3847.4 4184.02,3847.4 4204.69,3847.4 4225.36,3847.4 4246.03,3847.4 4266.7,3847.4 4287.37,3847.4 4308.04,3847.4 4328.71,3847.4 4349.38,3847.4 4370.05,3847.4 4631.73,3846.6 4786.58,3846.94 4872.84,3846.81 948.3,3848.15 1055.04,3848.23 1780.33,3848.18 3873,3848 3893,3848 4546.84,3848.09 4390.66,3849.02 5134.12,3848.51 731.26,3849.63 2938.75,3849.99 3041.45,3849.99 4709,3850 1483.66,3850.78 1816,3852 5087.36,3851.89 1367.72,3853.35 1976.4,3852.58 5021.46,3853.16 751.35,3854.46 1901,3855 4410.55,3854.62 4467.35,3854.8 4817.26,3854.91 771.94,3856.32 792.61,3856.34 813.28,3856.34 833.95,3856.34 854.62,3856.34 873.29,3856.34 891.93,3856.34 2024.68,3857.31 1209.7,3858.35 4582.28,3858.34 4663.49,3858.29 4740.48,3859.38 910.88,3859.97 4970.91,3860.33 4899.34,3862.46 1868,3863 5119.51,3863.12 1131.82,3864.02 4428.97,3864 962.82,3865.74 1339.6,3866.06 2944.99,3866.41 3035.25,3866.41 4865.77,3866.23 1024.36,3867.3 1101.14,3867.3 1177.92,3867.5 1514.34,3866.85 1945.72,3867.3 2054.09,3866.85 4633.02,3867.23 4709.8,3867.3 5072.75,3866.5 4553,3867.83 4786.58,3867.61 5006.84,3867.78 1055.04,3868.9 1787,3870 928.15,3871.34 1483.66,3871.45 4481.36,3871.63 1372.49,3873.46 1976.4,3873.25 1821,3874 1901,3876 4817.26,3875.58 4957.84,3876.34 4445.2,3876.8 1208.6,3878.17 2022.5,3877.86 4663.7,3877.9 5104.89,3877.74 4585.9,3878.68 4740.48,3880.05 5058.13,3881.12 4894.2,3882.48 4992.83,3881.79 2944.99,3882.68 3035.25,3882.68 972.09,3884.21 1131.82,3884.69 1342.66,3886.5 1986.5,3887 2053.18,3886.88 4863.37,3886.76 1024.36,3887.97 1101.14,3887.97 1177.92,3887.97 1514.34,3887.52 1868.94,3887.97 1945.72,3887.97 2009,3888 4555.96,3888.28 4633.02,3887.97 4709.8,3887.97 4786.58,3888.28 4492.53,3889.02 1055.04,3889.57 1373.34,3890.67 1483.66,3892.12 1792,3892 5090.28,3892.35 4458.63,3892.52 4663.7,3894.18 4948.13,3894.59 1823,3896 1900,3896 4817.26,3896.25 5043.52,3895.73 2990.12,3897.23 944.36,3897.82 1208.6,3898.17 4980.36,3898.28 4586.92,3899.33 4740.48,3900.72 4894.05,3902.43 977.24,3904.23 1131.82,3905.36 1342.66,3904.67 2883.94,3905.68 3096.26,3905.66 5075.66,3906.97 1514.34,3908.19 4501.1,3907.83 1024.36,3908.64 1101.14,3908.64 1177.92,3908.64 1373.34,3908.67 1868.94,3908.64 1945.72,3908.64 1976.4,3908.53 2053.18,3908.88 2978.12,3909.23 3002.12,3909.23 4326.89,3908.64 4357.37,3908.64 4387.85,3908.64 4418.33,3908.64 4443.81,3908.64 4556.24,3908.95 4633.02,3908.64 4709.8,3908.64 4786.58,3908.95 4863.37,3908.64 1055.04,3910.24 4468.97,3910.41 2022.5,3910.64 4942.01,3911 5030.06,3911.42 1792.16,3911.64 1483.66,3912.79 1822.84,3914.95 1899.62,3915.11 4663.7,3914.85 947.58,3916.24 4817.26,3916.61 4972.86,3917.54 1208.6,3918.84 4586.92,3920 4740.48,3921.39 4894,3921 5061.05,3921.59 978.26,3923.05 1342.68,3925.34 2053.18,3925.55 1373.52,3927.34 1976.4,3927.2 4506.9,3927.67 1024.36,3929.31 1101.14,3929.31 1177.92,3929.31 1512.89,3928.81 1792.16,3929.31 1868.94,3929.31 1945.72,3929.31 2022.5,3929.31 4326.89,3929.31 4357.37,3929.31 4387.85,3929.31 4418.33,3929.31 4448.81,3929.31 4609.97,3929.31 4633.02,3929.31 4686.59,3929.31 4709.8,3929.31 4763.37,3929.31 4786.58,3929.31 4840.31,3929.31 4863.36,3929.31 4917.09,3929.31 4940.45,3929.31 4475.91,3929.88 4556.24,3929.62 5020.99,3930 5077.98,3929.62 5108.46,3929.62 5138.94,3929.62 5169.42,3929.62 1001.31,3931.32 1078.09,3931.32 1131.82,3930.79 1154.87,3931.32 1231.65,3931.32 1252.7,3931.32 1270.04,3931.32 1287.38,3931.32 1308.43,3931.32 1671.28,3931.32 1692.33,3931.32 1713.38,3931.32 1730.72,3931.32 1748.06,3931.32 1769.11,3931.32 1845.89,3931.32 1922.67,3931.32 1999.45,3931.32 2076.23,3931.32 2097.28,3931.32 2114.62,3931.32 2131.96,3931.32 2153.01,3931.32 947.58,3932.98 1480.15,3933.16 2855.06,3934.57 3125.14,3934.55 1822.84,3935.62 1899.62,3935.78 4663.7,3935.52 4817.26,3937.28 5053.25,3938.35 1055.04,3939.16 4894.04,3939.31 4970.82,3938.94 1208.6,3939.68 4586.92,3940.36 978.26,3941.05 4740.48,3942.06 2053.64,3943 1346.36,3945.68 1381.41,3946.44 1976.4,3947.87 4509.8,3948.13 4532.86,3948.3 1507.06,3948.64 947.58,3949.98 1024.36,3949.98 1101.14,3949.98 1177.92,3949.98 1792.16,3949.98 1868.94,3949.98 1945.72,3949.98 2022.5,3949.98 4326.89,3949.98 4357.37,3949.98 4387.85,3949.98 4418.33,3949.98 4448.81,3949.98 4479.19,3950.29 4556.24,3949.98 4609.97,3949.98 4633.02,3949.98 4686.59,3949.98 4709.8,3949.98 4763.37,3949.98 4786.58,3949.98 4840.31,3949.98 4863.36,3949.98 4917.09,3949.98 4940.14,3949.98 4993.87,3949.98 5017.06,3949.98 5077.98,3950.29 5108.46,3950.29 5138.94,3950.29 5169.42,3950.29 828.8,3951.32 848.8,3951.32 868.8,3951.32 886.14,3951.32 903.48,3951.32 924.58,3951.32 1001.31,3951.32 1078.09,3951.32 1131.82,3951.46 1154.87,3951.32 1231.65,3951.32 1252.7,3951.32 1270.04,3951.32 1287.38,3951.32 1308.43,3951.32 1470.28,3951.32 1671.28,3951.32 1692.33,3951.32 1713.38,3951.32 1730.72,3951.32 1748.06,3951.32 1769.11,3951.32 1845.89,3951.32 1922.67,3951.32 1999.45,3951.32 2076.23,3951.32 2097.28,3951.32 2114.62,3951.32 2131.96,3951.32 2153.01,3951.32 5047.6,3955.02 1822.84,3956.29 1899.62,3956.45 4663.7,3956.19 4817.26,3957.95 978.26,3959.72 1055.04,3959.83 1208.6,3960.35 2053.64,3960 4894.04,3959.98 4970.82,3959.61 1396.3,3960.77 4586.92,3961.03 2883.94,3963.46 3096.26,3963.44 4740.48,3962.73 1356.11,3963.9 1455.02,3965.26 1497.05,3966.72 1976.4,3968.54 4510.14,3968.8 1414.84,3969.93 828.8,3971.32 848.8,3971.32 868.8,3971.32 886.14,3971.32 903.48,3971.32 924.58,3971.32 947.58,3970.65 1001.31,3971.32 1024.36,3970.65 1078.09,3971.32 1101.14,3970.65 1154.87,3971.32 1177.92,3970.65 1231.65,3971.32 1252.7,3971.32 1270.04,3971.32 1287.38,3971.32 1308.43,3971.32 1671.28,3971.32 1692.33,3971.32 1713.38,3971.32 1730.72,3971.32 1748.06,3971.32 1769.11,3971.32 1792.16,3970.65 1845.89,3971.32 1868.94,3970.65 1922.67,3971.32 1945.72,3970.65 1999.45,3971.32 2022.5,3970.65 2076.23,3971.32 2097.28,3971.32 2114.62,3971.32 2131.96,3971.32 2153.01,3971.32 4327.16,3970.65 4357.64,3970.65 4388.12,3970.65 4418.6,3970.65 4449.08,3970.65 4479.46,3970.96 4533.19,3970.96 4556.24,3970.65 4609.97,3970.65 4633.02,3970.65 4686.59,3970.65 4709.8,3970.65 4763.37,3970.65 4786.58,3970.65 4840.31,3970.65 4863.36,3970.65 4917.09,3970.65 4940.14,3970.65 4993.87,3970.65 5016.92,3970.65 5077.98,3970.65 5108.46,3970.65 5138.94,3970.65 5169.42,3970.65 1131.82,3972.13 1435.42,3971.82 5047.6,3975.38 978.8,3977 1055.8,3977 1209.8,3977 1822.84,3976.96 1899.62,3977.12 2053.64,3977 4663.7,3976.86 4818,3976.69 4895,3976.69 4971,3976.69 4586.92,3977.7 1370.3,3978.94 1483.36,3982.21 828.8,3991.32 848.8,3991.32 868.8,3991.32 903.48,3991.32 924.58,3991.32 945.58,3991.32 1001.31,3991.32 1022.36,3991.32 1078.09,3991.32 1099.14,3991.32 1154.87,3991.32 1175.92,3991.32 1231.65,3991.32 1252.7,3991.32 1287.38,3991.32 1308.43,3991.32 1386.91,3991.23 1671.28,3991.32 1692.33,3991.32 1713.38,3991.32 1748.06,3991.32 1769.11,3991.32 1790.16,3991.32 1845.89,3991.32 1866.94,3991.32 1922.67,3991.32 1943.72,3991.32 1999.45,3991.32 2020.5,3991.32 2076.23,3991.32 2097.28,3991.32 2131.96,3991.32 2153.01,3991.32 4327.16,3991.32 4357.64,3991.32 4388.12,3991.32 4449.08,3991.32 4477.46,3991.32 4533.19,3991.32 4554.24,3991.32 4609.97,3991.32 4631.02,3991.32 4686.59,3991.32 4707.8,3991.32 4763.37,3991.32 4784.58,3991.32 4840.31,3991.32 4861.36,3991.32 4917.09,3991.32 4938.14,3991.32 4993.87,3991.32 5014.92,3991.32 5077.98,3991.32 5138.94,3991.32 5169.42,3991.32 1134.8,3992 1978.64,3993 980.8,3994 1056.8,3994 1210.8,3994 1466.4,3994.02 1824.64,3994 1901.64,3994 2055.64,3994 4512.14,3994.05 4588.92,3994.05 4665.7,3994.05 4742.48,3994.05 4896,3993.69 4974,3993.69 5051,3993.69 4819,3994.69 1405.95,3999.3 1446.94,4001 1426.34,4002.68 828.8,4010.99 848.8,4010.99 868.8,4010.99 903.48,4011.05 924.58,4010.99 945.58,4010.99 980.26,4011.05 1001.31,4010.99 1022.36,4010.99 1057.04,4011.05 1078.09,4010.99 1099.14,4010.99 1133.82,4011.05 1154.87,4010.99 1175.92,4010.99 1210.6,4011.05 1231.65,4010.99 1252.7,4010.99 1287.38,4011.05 1308.43,4011.05 1671.28,4010.99 1692.33,4010.99 1713.38,4010.99 1748.06,4011.05 1769.11,4011.05 1790.16,4010.99 1824.84,4011.05 1845.89,4011.05 1866.94,4010.99 1901.62,4011.05 1922.67,4011.05 1943.72,4010.99 1978.4,4011.05 1999.45,4011.05 2020.5,4010.99 2055.18,4011.05 2076.23,4011.05 2097.28,4010.99 2131.96,4011.05 2153.01,4011.05 4477.46,4010.99 4512.14,4011.05 4554.24,4010.99 4588.92,4011.05 4631.02,4010.99 4665.7,4011.05 4707.8,4010.99 4742.48,4011.05 4784.58,4010.99 4819.26,4011.05 4861.36,4010.99 4896.04,4011.05 4938.14,4010.99 4972.82,4011.05 5014.92,4010.99 5049.6,4011.05 4327.16,4011.99 4357.64,4011.99 4388.12,4011.99 4449.08,4011.99 4533.19,4011.99 4609.97,4011.99 4686.59,4011.99 4763.37,4011.99 4840.31,4011.99 4917.09,4011.99 4993.87,4011.99 5077.98,4011.99 5138.94,4011.99 5169.42,4011.99
  other v2: 194.43,-88.31 264.43,-88.31 334.43,-88.31 404.43,-88.31 474.43,-88.31 544.42,-88.31 614.42,-88.31 684.42,-88.31 754.42,-88.31 824.42,-88.31 894.42,-88.31 964.42,-88.31 1034.41,-88.31 1104.41,-88.31 1174.41,-88.31 1244.41,-88.31 1314.41,-88.31 1384.41,-88.31 1454.41,-88.31 1524.41,-88.31 1594.4,-88.31 1664.4,-88.31 1734.4,-88.31 1804.4,-88.31 1874.4,-88.31 1944.4,-88.31 2014.4,-88.31 2084.39,-88.31 2154.39,-88.31 2224.39,-88.31 2294.39,-88.31 2364.39,-88.31 2434.39,-88.31 2504.39,-88.31 2574.38,-88.31 2644.38,-88.31 2714.38,-88.31 2784.38,-88.31 2854.38,-88.31 2924.38,-88.31 2994.38,-88.31 3064.37,-88.31 3134.37,-88.31 3204.37,-88.31 3274.37,-88.31 3344.37,-88.31 3414.37,-88.31 3484.37,-88.31 3554.36,-88.31 3624.36,-88.31 3694.36,-88.31 3764.36,-88.31 3834.36,-88.31 3904.36,-88.31 3974.36,-88.31 4044.35,-88.31 4114.35,-88.31 4184.35,-88.31 4254.35,-88.31 4324.35,-88.31 4394.35,-88.31 4464.35,-88.31 4534.35,-88.31 4604.34,-88.31 4674.34,-88.31 4744.34,-88.31 4814.34,-88.31 4884.34,-88.31 4954.34,-88.31 5024.34,-88.31 5094.33,-88.31 5164.33,-88.31 5234.33,-88.31 5304.33,-88.31 5374.33,-88.31 5444.33,-88.31 5514.33,-88.31 5584.32,-88.31 5654.32,-88.31 5724.32,-88.31 5794.32,-88.31 5864.32,-88.31 5286.85,8.84 5286.85,38.8 5292.5,75.61 5322.45,75.61 5315.23,134.73 5315.23,164.68 -88.31,194.43 5729.21,204.53 5759.16,204.53 5808.48,228.47 5838.43,228.47 5875.63,242.42 5902.94,242.23 5360.63,256.03 5435.96,256.03 5511.29,256.03 5586.63,256.03 -88.31,264.43 5322.96,297.53 5398.29,297.53 5473.63,297.53 5548.96,297.53 5624.29,297.53 -88.31,334.43 5360.63,339.03 5435.96,339.03 5511.29,339.03 5586.63,339.03 -88.31,404.43 -88.31,474.43 -88.31,544.42 363.74,600.23 397.08,600.23 430.41,600.23 -88.31,614.42 -88.31,684.42 4923.43,741.29 4953.38,741.29 4989.42,750.89 5019.37,750.89 5073.16,751.52 5103.11,751.52 -88.31,754.42 -88.31,824.42 -88.31,894.42 -88.31,964.42 -88.31,1034.41 489.9,1043.88 565.24,1043.88 640.57,1043.88 715.9,1043.88 114.64,1084.79 452.24,1085.38 527.57,1085.38 602.9,1085.38 678.24,1085.38 753.57,1085.38 1051.66,1100.45 1081.61,1100.45 -88.31,1104.41 114.64,1114.74 489.9,1126.88 565.24,1126.88 640.57,1126.88 715.9,1126.88 101.38,1146.98 1056.79,1161.82 1086.74,1161.82 -88.31,1174.41 101.38,1176.93 4325.94,1177.24 4373.38,1177.24 5061.5,1190.19 5088.82,1190 5117.84,1190 4995.8,1204.21 5025.75,1204.21 79.9,1210.19 4373.38,1223 4924.05,1222.88 4954,1222.88 4326.78,1223.84 1087.18,1227.36 79.71,1237.5 -88.31,1244.41 1087.37,1254.68 1127,1455.4 1099.68,1455.59 1033.7,1469.73 1061.01,1469.54 4950.43,1471.54 974.56,1493.36 947.24,1493.55 4950.43,1500.56 4950.62,1527.88 4972.11,1561.14 4972.11,1591.09 5360.63,1611.18 5435.96,1611.18 5511.29,1611.18 5586.63,1611.18 4985.36,1623.33 4985.36,1653.28 5322.96,1652.68 5398.29,1652.68 5473.63,1652.68 5548.96,1652.68 5624.29,1652.68 5360.63,1694.18 5435.96,1694.18 5511.29,1694.18 5586.63,1694.18 5557.39,1764.68 5557.2,1791.99 5557.2,1821.02 5573.77,1868.27 5573.77,1898.22 5592.96,1932.66 5592.96,1962.61 115.16,2037.09 115.16,2067.04 101.2,2094.29 101.2,2124.24 6125.31,2154.39 79.71,2164.14 79.71,2193.16 79.9,2220.47 6125.31,2224.39 79.71,2259.4 1010.97,2286.94 1084.52,2287.44 79.71,2288.42 6125.31,2294.39 79.9,2315.73 101.38,2348.99 6125.31,2364.39 101.38,2378.95 1304,2396 1364,2398 489.9,2399.04 565.24,2399.04 640.57,2399.04 715.9,2399.04 114.64,2411.18 4674.4,2418.5 6125.31,2434.39 114.64,2441.14 452.24,2440.54 527.57,2440.54 602.9,2440.54 678.24,2440.54 753.57,2440.54 1421,2456.6 489.9,2482.04 565.24,2482.04 640.57,2482.04 715.9,2482.04 4586,2489 1206.6,2496 1243,2496 6125.31,2504.39 4838,2505 1129.6,2509 1166,2509 4754,2509 4700,2510 2353,2511.88 2539.75,2518.13 2516.78,2539.1 3624,2539.99 3825.42,2550.09 2494.1,2554.23 4844,2561 4602,2565 3810.74,2575.49 3840.09,2575.49 3578,2578.99 2267,2580.88 3697,2592.99 4557,2597 2436,2602.88 2382,2603.88 2284,2658.88 3599,2658.99 2666.94,2668.19 2696.64,2668.19 2239,2690.88 3554,2690.99 2156,2706.88 2828.14,2716.33 2628.42,2751.48 2674.18,2751.48 3389.76,2759.92 6125.31,2784.38 3942.36,2788.3 2675.02,2798.08 2628.42,2798.92 3910.01,2820.66 3975.91,2820.66 280.98,2836.75 308.29,2836.94 335.61,2837.13 3943.55,2854.2 6125.31,2854.38 280.79,2864.06 308.1,2864.25 335.42,2864.44 4745.08,2905.92 1358.79,2907.3 1228.79,2924.22 6125.31,2924.38 1283.49,2925.9 4771.49,2925.9 1331.59,2927.9 4819.59,2927.9 1358.79,2935.7 4846.79,2935.7 1333.09,2979.1 4821.09,2979.1 6125.31,2994.38 2427.08,2999.92 2528.79,3001.3 3843.79,3001.3 1253.44,3006.81 4741.44,3006.81 1312.89,3007.7 4800.89,3007.7 2398.79,3018.22 3713.79,3018.22 2501.59,3021.9 3816.59,3021.9 2528.79,3029.7 3843.79,3029.7 6125.31,3064.37 2503.09,3073.1 3818.09,3073.1 2423.44,3100.81 3738.44,3100.81 2482.89,3101.7 3797.89,3101.7 6125.31,3134.37 4948,3144.65 4933.24,3183.92 1454.85,3190.5 1388.55,3212.28 1434.31,3212.28 4965.6,3216.27 4933.24,3249.82 1435.15,3258.88 1388.55,3259.72 2621.12,3287.28 2666.88,3287.28 2621.12,3334.72 2583.59,3341.06 6125.31,3344.37 3918.26,3349.73 2615.95,3373.42 2550.05,3374.6 3919.1,3396.33 3872.5,3397.17 3359.58,3402.57 3405.34,3402.57 2583.59,3406.96 6125.31,3414.37 3406.18,3449.17 3358.58,3450.01 3346.87,3480.29 3418.07,3480.29 -88.31,3484.37 6125.31,3484.37 -88.31,3554.36 6125.31,3554.36 -88.31,3624.36 6125.31,3624.36 3317.77,3642.85 3447.15,3642.85 2967.22,3644.58 3012.98,3644.58 3299.18,3667.84 3465.74,3667.82 3253.42,3668.84 3511.5,3668.82 3365.84,3689.22 3399.08,3689.22 3013.82,3691.18 2966.22,3692.02 6125.31,3694.36 3335.3,3708.17 3429.62,3708.15 3252.58,3715.44 3512.34,3715.42 3299.18,3717.28 3465.74,3717.26 2954.51,3722.3 3025.71,3722.3 6125.31,3764.36 6125.31,3834.36 2925.41,3884.86 3054.79,3884.86 6125.31,3904.36 2906.82,3909.85 3073.38,3909.83 2861.06,3910.85 3119.14,3910.83 2973.48,3931.23 3006.72,3931.23 2942.94,3950.18 3037.26,3950.16 2860.22,3957.45 3119.98,3957.43 2906.82,3959.29 3073.38,3959.27 6125.31,3974.36 6125.31,4044.35 6125.31,4114.35 6125.31,4184.35 6125.31,4254.35 -88.31,4324.35 6125.31,4324.35 6125.31,4394.35 6125.31,4464.35 6125.31,4534.35 6125.31,4604.34 6125.31,4674.34 6125.31,4744.34 6125.31,4814.34 6125.31,4884.34 6125.31,4954.34 194.43,5196.31 264.43,5196.31 334.43,5196.31 404.43,5196.31 474.43,5196.31 544.42,5196.31 614.42,5196.31 684.42,5196.31 5282.79,5196.31 5352.79,5196.31 5422.79,5196.31 5492.79,5196.31 5562.78,5196.31 5632.78,5196.31 5702.78,5196.31 5772.78,5196.31 5842.78,5196.31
